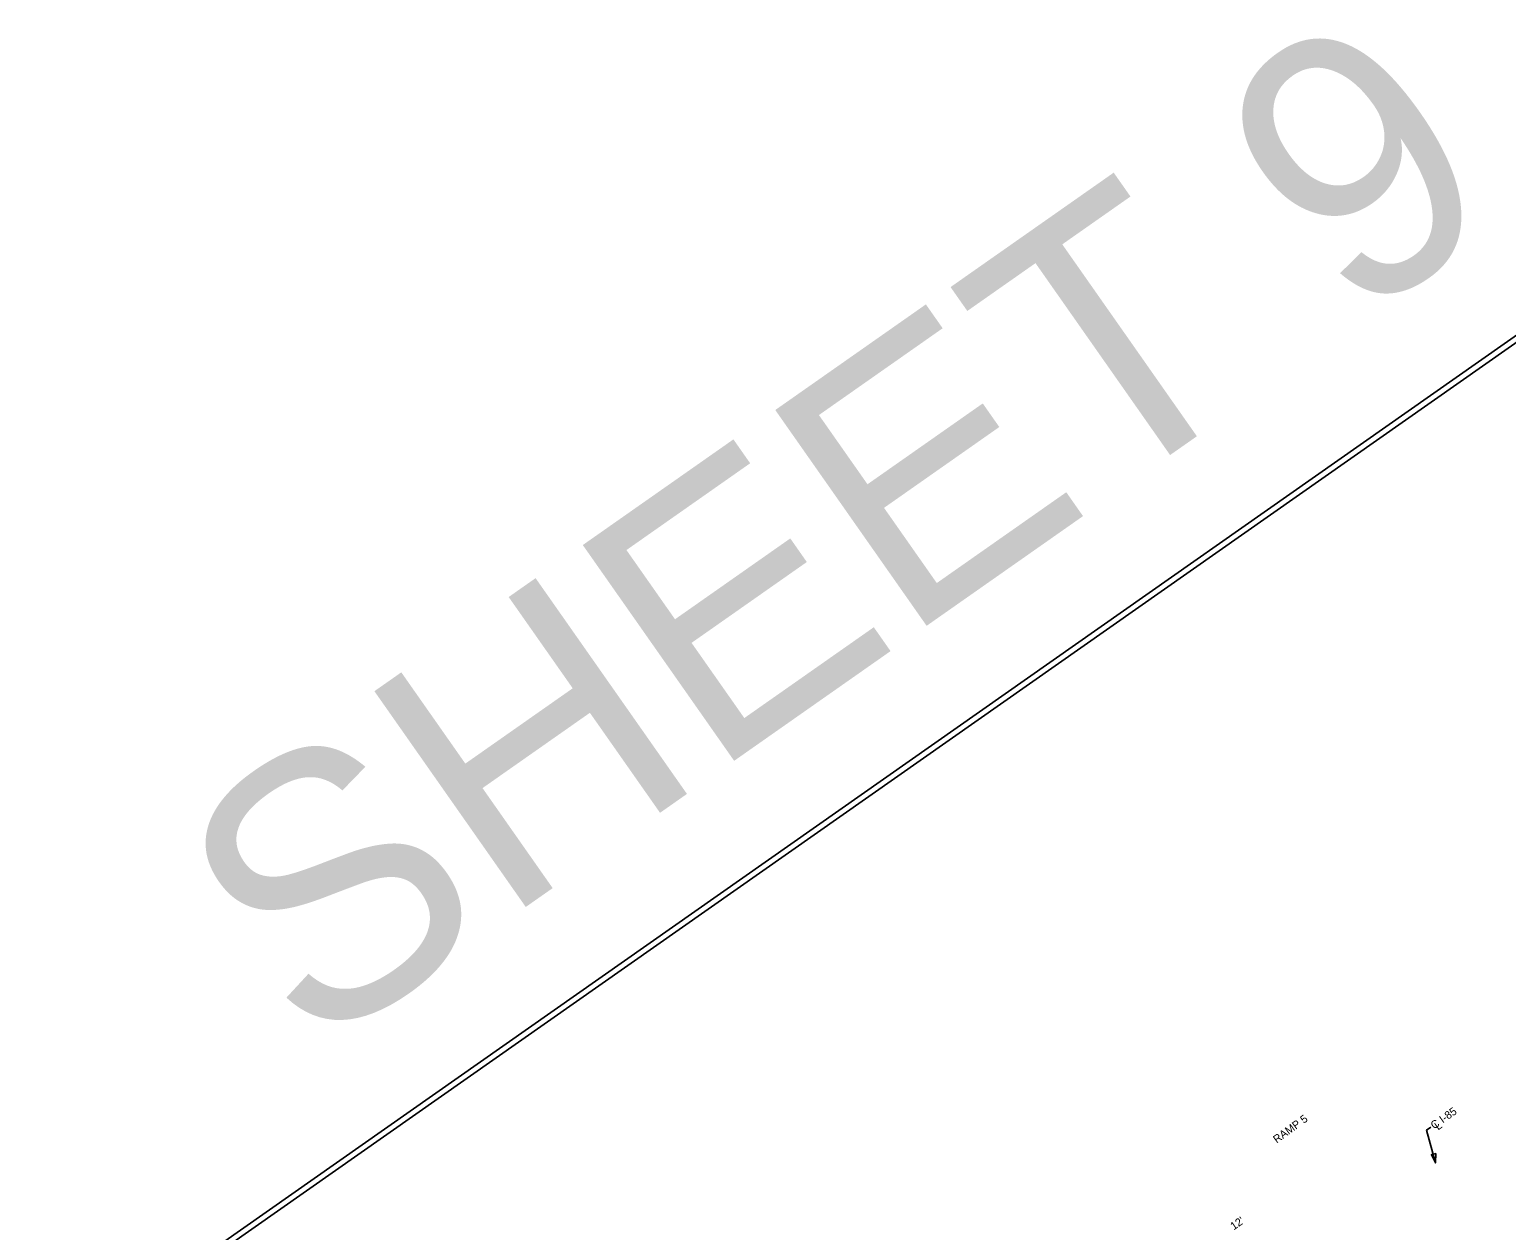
# Model space of a CAD drawing. Extents: x 1606191 to 1608111, y 1090371 to 1092208.
# Drawn here: x 1606191 to 1607311, y 1091296 to 1092208 of the extents above; entities that cross this region are included whole.
import ezdxf

# ---------------------------------------------------------------- set-up
doc = ezdxf.new("R2010")
doc.units = 0
for name, color, linetype in [('Copy of RD_HC_SUR_Distance_TX200', 7, 'Continuous'), ('RD_EX_Fence_Other', 7, 'Continuous'), ('RD_EX_Misc_Golf_Teebox', 7, 'Continuous'), ('RD_EX_TopoTX', 7, 'Continuous'), ('V-BLDG-OTLN', 7, 'Continuous')]:
    doc.layers.add(name, color=color, linetype=linetype)

msp = doc.modelspace()

# ---------------------------------------------------------------- linework, layer by layer
at = {"layer": 'RD_EX_Fence_Other'}
msp.add_lwpolyline([(1606190.8, 1091184.3), (1607562.1, 1092146.2), (1608111.3, 1091363.1), (1606740.1, 1090401.3)], close=True, dxfattribs=at)
at = {"layer": 'RD_EX_TopoTX'}
msp.add_lwpolyline([(1607257.5, 1091347.5), (1607250.8, 1091372.4), (1607254, 1091374.6)], dxfattribs=at)
msp.add_lwpolyline([(1607257.9, 1091354.6), (1607254.5, 1091353.9), (1607257.5, 1091347.5)], close=True, dxfattribs=at)
at = {"layer": 'V-BLDG-OTLN'}
msp.add_lwpolyline([(1606406.7, 1091049.1), (1606535.9, 1090871.8), (1606533, 1090870.5), (1606692.3, 1090643.6), (1606817.6, 1090464.9), (1608054.2, 1091332.3), (1607913.9, 1091514), (1607741.1, 1091760.4), (1607743.5, 1091761.6), (1607623.7, 1091926), (1607395.6, 1091983.6), (1607376.3, 1092010.2), (1606278.9, 1091240.8)], close=True, dxfattribs=at)
msp.add_lwpolyline([(1606406.7, 1091049.1), (1606535.9, 1090871.8), (1606533, 1090870.5), (1606692.3, 1090643.6), (1606817.6, 1090464.9), (1608054.2, 1091332.3), (1607913.9, 1091514), (1607741.1, 1091760.4), (1607743.5, 1091761.6), (1607623.7, 1091926), (1607395.6, 1091983.6), (1607376.3, 1092010.2), (1606278.9, 1091240.8)], close=True, dxfattribs=at)

# ---------------------------------------------------------------- texts
at = {"layer": 'Copy of RD_HC_SUR_Distance_TX200'}
msp.add_text('SHEET 9', height=200, rotation=35.0468, dxfattribs=at).set_placement((1606403.3, 1091426.7))
at = {"layer": 'RD_EX_Misc_Golf_Teebox'}
msp.add_text("12'", height=6, rotation=35.0436, dxfattribs=at).set_placement((1607104.5, 1091296.3))
at = {"layer": 'RD_EX_TopoTX'}
for s, rotation, p in [('RAMP 5', 36.0638, (1607137.1, 1091362.2)), ('C I-85', 35.0535, (1607256.5, 1091372.8)), ('L', 35.0535, (1607259.5, 1091372.1))]:
    msp.add_text(s, height=6, rotation=rotation, dxfattribs=at).set_placement(p)

doc.saveas('drawing.dxf')
